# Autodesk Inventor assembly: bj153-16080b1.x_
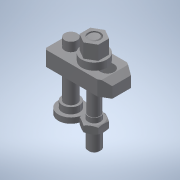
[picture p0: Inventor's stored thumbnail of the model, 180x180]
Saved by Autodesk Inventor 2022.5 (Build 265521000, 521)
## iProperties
Part Number: bj153-16080b1.x_
Material: 一般
Document SubType Name: Assembly
Designer: ImaoCorp
Sending System: SOLIDWORKS 2017-2017317
MC: AMD64
MC_MODEL: Intel64 Family 6 Model 60 Stepping 3, GenuineIntel
OS: Windows_NT
FRU: Parasolid Version 29.0, build 201,  4-17-2017
FORMAT: text
GUISE: transmit
KEY: bj153-16080b1
FILE: bj153-16080b1.x_t
DATE: Fri Mar 15 10:24:03 2019
Author: ImaoCorp
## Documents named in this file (6)
- X:\14_SW2022-Inv2022\00_全2023-1023新製品(TCC)まで\b\bj153-16080b1\BJ153-16080B1.iam
- X:\14_SW2022-Inv2022\00_全2023-1023新製品(TCC)まで\b\bj153-16080b1\bj153-16080b1_01.ipt
- X:\14_SW2022-Inv2022\00_全2023-1023新製品(TCC)まで\b\bj153-16080b1\bj153-16080b1_02.ipt
- X:\14_SW2022-Inv2022\00_全2023-1023新製品(TCC)まで\b\bj153-16080b1\bj153-16080b1_03.ipt
- X:\14_SW2022-Inv2022\00_全2023-1023新製品(TCC)まで\b\bj153-16080b1\bj153-16080b1_04.ipt
- X:\14_SW2022-Inv2022\00_全2023-1023新製品(TCC)まで\b\bj153-16080b1\bj153-16080b1_05.ipt
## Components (5 placed, 5 different names)
1. bj153-16080b1_01
2. bj153-16080b1_02
3. bj153-16080b1_03
4. bj153-16080b1_04
5. bj153-16080b1_05
